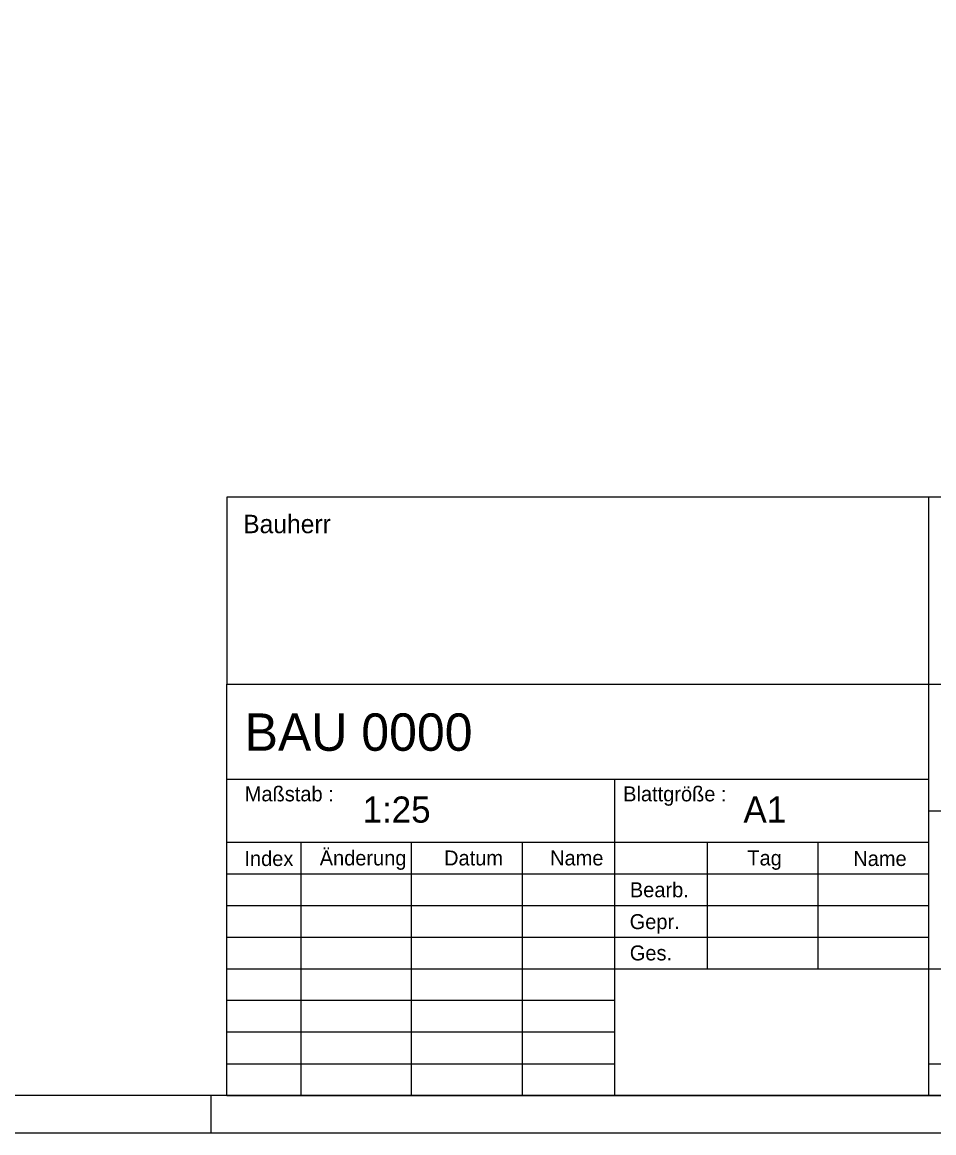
# Model space of a CAD drawing. Extents: x 0 to 21, y 0 to 14.9.
# Drawn here: x 15.769 to 18.816, y 0 to 3.713 of the extents above; entities that cross this region are included whole.
import ezdxf

# ---------------------------------------------------------------- set-up
doc = ezdxf.new("R2010")
doc.units = 0
doc.layers.add('90_Plankopf', color=7, linetype='Continuous')

msp = doc.modelspace()

# ---------------------------------------------------------------- linework, layer by layer
at = {"layer": '90_Plankopf'}
for p, q in [((20.9, 2.1248), (16.453, 2.1248)), ((16.453, 2.1248), (16.453, 1.4998)), ((18.8, 1.4998), (18.8, 2.1248)), ((16.453, 1.4998), (20.9, 1.4998)), ((16.453, 0.125), (16.453, 1.4998)), ((16.453, 1.4998), (20.9, 1.4998)), ((18.8, 0.125), (18.8, 1.4998)), ((16.453, 1.1825), (18.8, 1.1825)), ((17.7501, 0.125), (17.7501, 1.1825)), ((18.8, 1.0768), (20.9, 1.0768)), ((16.453, 0.9718), (18.8, 0.9718)), ((16.7001, 0.971), (16.7001, 0.125)), ((17.0707, 0.125), (17.0707, 0.971)), ((17.4412, 0.125), (17.4412, 0.971)), ((18.0589, 0.971), (18.0589, 0.548)), ((18.4295, 0.548), (18.4295, 0.971)), ((16.453, 0.8658), (18.8, 0.8658)), ((16.453, 0.7595), (18.8, 0.7595)), ((16.453, 0.6538), (18.8, 0.6538)), ((16.453, 0.548), (18.8, 0.548)), ((16.453, 0.548), (18.8, 0.548)), ((17.7501, 0.548), (18.8, 0.548)), ((18.8, 0.548), (20.9, 0.548)), ((17.7501, 0.4423), (16.453, 0.4423)), ((17.7501, 0.3365), (16.453, 0.3365)), ((16.453, 0.2308), (17.7501, 0.2308)), ((18.8, 0.2308), (20.9, 0.2308)), ((16.4, 0), (16.4, 0.125)), ((20.9, 0.125), (16.453, 0.125)), ((16.453, 0.125), (17.7501, 0.125)), ((16.745, 0.125), (20.9, 0.125)), ((16.745, 0.125), (20.9, 0.125))]:
    msp.add_line(p, q, dxfattribs=at)
for points in [[(0, 0), (21.025, 0), (21.025, 14.85), (0, 14.85)], [(0.625, 14.725), (20.9, 14.725), (20.9, 0.125), (0.625, 0.125)]]:
    msp.add_lwpolyline(points, close=True, dxfattribs=at)

# ---------------------------------------------------------------- texts
for s, height, p in [('Bauherr', 0.06159, (16.5076, 2.0044)), ('BAU 0000      ', 0.125, (16.5123, 1.2769)), ('Maßstab :', 0.05, (16.5129, 1.1079)), ('Blattgröße :', 0.049998, (17.7779, 1.1079)), ('1:25     ', 0.0875, (16.9065, 1.0367)), ('A1       ', 0.0875, (18.18, 1.0367)), ('Index', 0.05, (16.5117, 0.8918)), ('Änderung', 0.05, (16.7634, 0.8937)), ('Datum', 0.05, (17.1792, 0.8937)), ('Name', 0.05, (17.5337, 0.8937)), ('Tag', 0.05, (18.1931, 0.8937)), ('Name', 0.05, (18.5473, 0.8918)), ('Bearb.', 0.05, (17.8004, 0.7873)), ('Gepr.', 0.05, (17.7997, 0.6808)), ('Ges.', 0.05, (17.8001, 0.5762))]:
    msp.add_text(s, height=height, dxfattribs=at).set_placement(p)

doc.saveas('drawing.dxf')
